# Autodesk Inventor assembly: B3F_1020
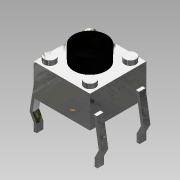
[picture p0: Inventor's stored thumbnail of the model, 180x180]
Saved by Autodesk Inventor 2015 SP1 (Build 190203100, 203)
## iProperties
Created: 2015-05
Part Number: B3F_1020
Document SubType Name: Assembly
Designer: kazys
Author: kazys
Author: OSMC1.0   TAKUMI
Title: B3F_1020.step
Organization: TAKUMI-Engniaring
Description: STEP AP203
Creation Date: 2013-07-18
Sending System: SolidWorks 2002025
Preprocessor: SwSTEP 2.0
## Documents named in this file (3)
- C:\Users\kazys\Documents\Inventor\Clock\B3F_1020.iam
- C:\Users\kazys\Documents\Inventor\Clock\Imported Components\B3F_1020\B3F_1020_BUTTON.ipt
- C:\Users\kazys\Documents\Inventor\Clock\Imported Components\B3F_1020\B3F_1020_BASE.ipt
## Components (2 placed, 2 different names)
1. B3F_1020_BUTTON_1
2. B3F_1020_BASE_2
